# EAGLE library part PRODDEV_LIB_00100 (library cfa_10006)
CFAG12864A-YYH-VN, 128x64 Yellow/Green STN, Positive, Transflective, LED Array Backlit LCD Module
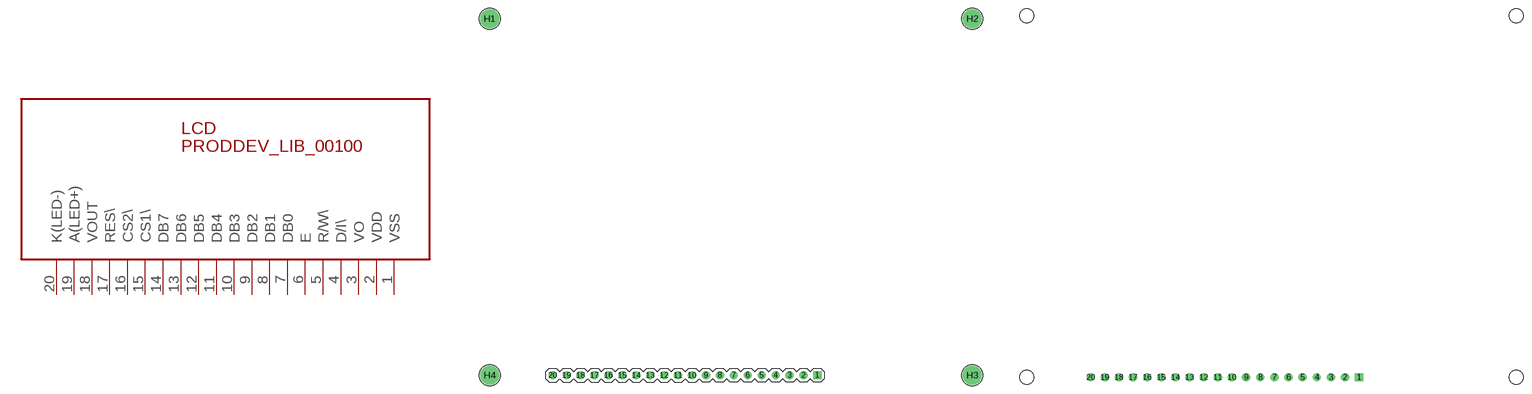
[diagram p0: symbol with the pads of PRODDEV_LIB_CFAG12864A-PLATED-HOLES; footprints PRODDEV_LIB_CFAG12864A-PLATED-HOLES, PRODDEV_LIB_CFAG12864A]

Designator prefix LCD

## PRODDEV_LIB_00100  [PRODDEV_LIB_CFAG12864A-PLATED-HOLES]
1  VSS  pwr
2  VDD  pwr
3  VO  pas
4  D/I\  in
5  R/W\  in
6  E  in
7  DB0
8  DB1
9  DB2
10  DB3
11  DB4
12  DB5
13  DB6
14  DB7
15  CS1\  in
16  CS2\  in
17  RES\  in
18  VOUT  pas
19  A(LED+)  pas
20  K(LED-)  pas

## PRODDEV_LIB_00100NP  [PRODDEV_LIB_CFAG12864A]
Pads as for PRODDEV_LIB_CFAG12864A-PLATED-HOLES

## Footprint PRODDEV_LIB_CFAG12864A-PLATED-HOLES (pad centres in mm)
drill 1 square: 1 0,0
drill 1 round: 2 -2.54,0; 3 -5.08,0; 4 -7.62,0; 5 -10.16,0; 6 -12.7,0; 7 -15.24,0; 8 -17.78,0; 9 -20.32,0; 10 -22.86,0; 11 -25.4,0; 12 -27.94,0; 13 -30.48,0; 14 -33.02,0; 15 -35.56,0; 16 -38.1,0; 17 -40.64,0; 18 -43.18,0; 19 -45.72,0; 20 -48.26,0
drill 2.5 round: H1 -59.76,65; H2 28.24,65; H3 28.24,0; H4 -59.76,0

## Footprint PRODDEV_LIB_CFAG12864A (pad centres in mm)
drill 1 square: 1 0,0
drill 1 round: 2 -2.54,0; 3 -5.08,0; 4 -7.62,0; 5 -10.16,0; 6 -12.7,0; 7 -15.24,0; 8 -17.78,0; 9 -20.32,0; 10 -22.86,0; 11 -25.4,0; 12 -27.94,0; 13 -30.48,0; 14 -33.02,0; 15 -35.56,0; 16 -38.1,0; 17 -40.64,0; 18 -43.18,0; 19 -45.72,0; 20 -48.26,0
hole 2.5 at -59.76,0
hole 2.5 at 28.24,0
hole 2.5 at 28.24,65
hole 2.5 at -59.76,65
